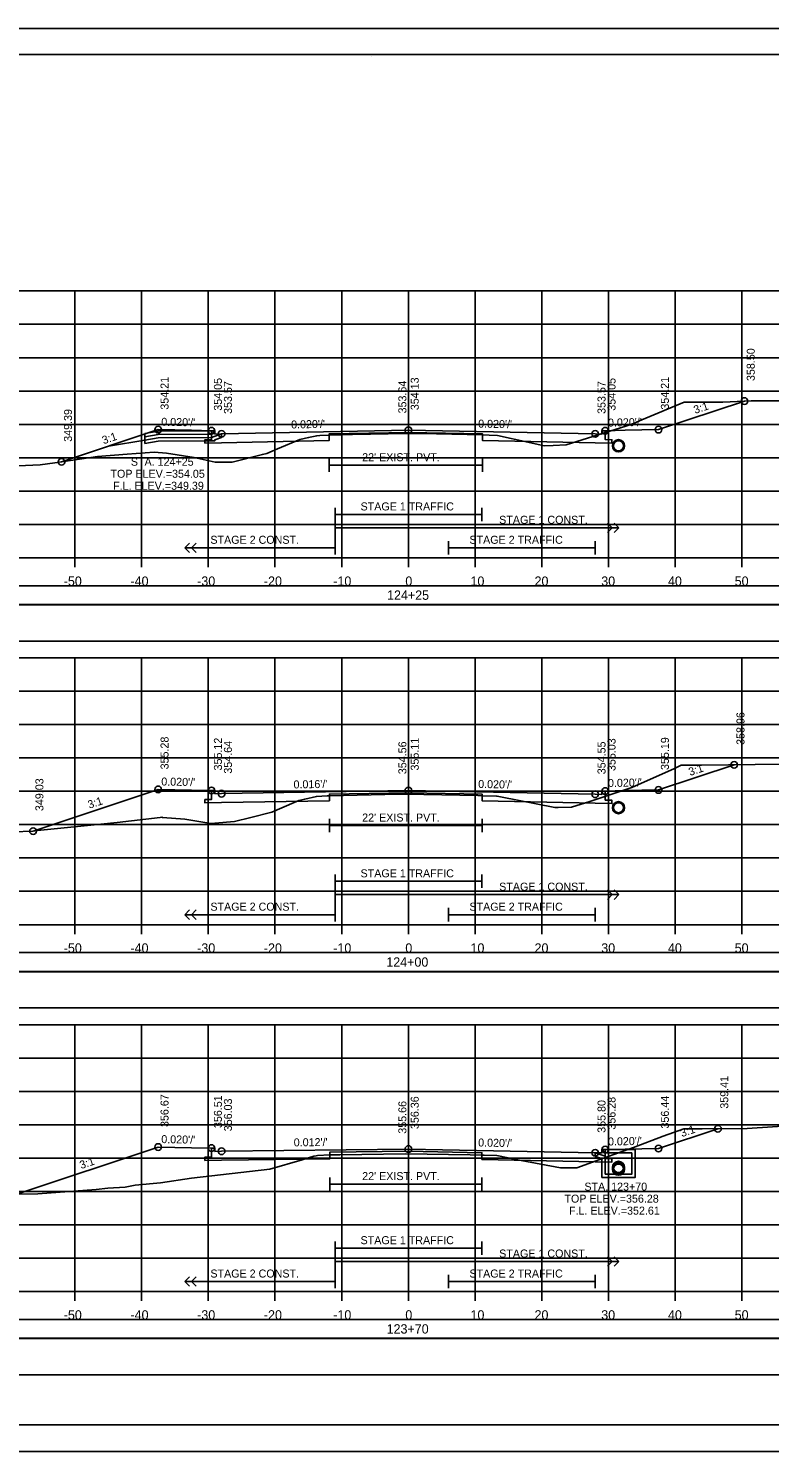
# Model space of a CAD drawing. Extents: x 1368122 to 1710785, y 373130 to 557566.
# Drawn here: x 1368631.9 to 1368743, y 376330.4 to 376543.7 of the extents above; entities that cross this region are included whole.
import ezdxf

# ---------------------------------------------------------------- set-up
doc = ezdxf.new("R2010")
doc.units = 0
for name, color, linetype in [('R_Alt Surface', 7, 'Continuous'), ('R_Axis', 7, 'Continuous'), ('R_Axis Annot', 7, 'Continuous'), ('R_Border', 7, 'Continuous'), ('R_Exist Surface', 7, 'Continuous'), ('R_Fin Surface', 7, 'Continuous'), ('R_Grid', 7, 'Continuous'), ('R_No Plot', 7, 'Continuous'), ('R_Striping', 7, 'Continuous'), ('R_Water', 7, 'Continuous'), ('R_Water Annot', 7, 'Continuous'), ('R_Xsect Elev', 7, 'Continuous'), ('R_Xsect Slope', 7, 'Continuous')]:
    doc.layers.add(name, color=color, linetype=linetype)

msp = doc.modelspace()

# ---------------------------------------------------------------- linework, layer by layer
for points in [[(1368539.73, 376451.9), (1368838.03, 376451.9), (1368838.03, 376457.32), (1368539.73, 376457.32)], [(1368539.73, 376396.9), (1368838.03, 376396.9), (1368838.03, 376402.32), (1368539.73, 376402.32)], [(1368539.73, 376341.9), (1368838.03, 376341.9), (1368838.03, 376347.32), (1368539.73, 376347.32)]]:
    msp.add_lwpolyline(points, close=True)
at = {"layer": 'R_Alt Surface'}
for points in [[(1368718.38, 376483.43), (1368718.38, 376482.09), (1368719.38, 376482.07), (1368719.38, 376481.57), (1368716.88, 376481.62), (1368700.01, 376481.96), (1368700.01, 376482.96), (1368688.88, 376483.18), (1368676.99, 376482.94), (1368676.99, 376481.94), (1368660.88, 376481.62), (1368658.38, 376481.57), (1368658.38, 376482.07), (1368659.38, 376482.09), (1368659.38, 376483.43)], [(1368676.99, 376479.26), (1368676.99, 376477.26)], [(1368700.01, 376479.26), (1368700.01, 376477.26)], [(1368676.99, 376478.26), (1368700.01, 376478.26)], [(1368718.38, 376429.41), (1368718.38, 376428.06), (1368719.38, 376428.04), (1368719.38, 376427.54), (1368716.88, 376427.59), (1368699.96, 376427.93), (1368699.96, 376428.93), (1368688.88, 376429.16), (1368677.04, 376428.96), (1368677.04, 376427.96), (1368660.88, 376427.69), (1368658.38, 376427.64), (1368658.38, 376428.14), (1368659.38, 376428.16), (1368659.38, 376429.5)], [(1368677.04, 376425.24), (1368677.04, 376423.24)], [(1368677.04, 376424.24), (1368699.96, 376424.24)], [(1368699.96, 376425.24), (1368699.96, 376423.24)], [(1368718.38, 376375.66), (1368718.38, 376374.32), (1368719.38, 376374.3), (1368719.38, 376373.8), (1368716.88, 376373.85), (1368699.9, 376374.19), (1368699.9, 376375.19), (1368688.88, 376375.41), (1368677.09, 376375.27), (1368677.09, 376374.27), (1368660.88, 376374.08), (1368658.38, 376374.03), (1368658.38, 376374.53), (1368659.38, 376374.55), (1368659.38, 376375.89)], [(1368677.09, 376371.49), (1368677.09, 376369.49)], [(1368677.09, 376370.49), (1368699.9, 376370.49)], [(1368699.9, 376371.49), (1368699.9, 376369.49)]]:
    msp.add_lwpolyline(points, dxfattribs=at)
for points in [[(1368539.73, 376457.37), (1368838.03, 376457.37), (1368838.03, 376460.19), (1368539.73, 376460.19)], [(1368539.73, 376402.37), (1368838.03, 376402.37), (1368838.03, 376405.19), (1368539.73, 376405.19)], [(1368539.73, 376347.37), (1368838.03, 376347.37), (1368838.03, 376350.19), (1368539.73, 376350.19)]]:
    msp.add_lwpolyline(points, close=True, dxfattribs=at)
at = {"layer": 'R_Axis'}
for p, q in [((1368538.88, 376464.38), (1368838.88, 376464.38)), ((1368638.88, 376462.98), (1368638.88, 376464.38)), ((1368648.88, 376462.98), (1368648.88, 376464.38)), ((1368658.88, 376462.98), (1368658.88, 376464.38)), ((1368668.88, 376462.98), (1368668.88, 376464.38)), ((1368678.88, 376462.98), (1368678.88, 376464.38)), ((1368688.88, 376462.98), (1368688.88, 376464.38)), ((1368698.88, 376462.98), (1368698.88, 376464.38)), ((1368708.88, 376462.98), (1368708.88, 376464.38)), ((1368718.88, 376462.98), (1368718.88, 376464.38)), ((1368728.88, 376462.98), (1368728.88, 376464.38)), ((1368738.88, 376462.98), (1368738.88, 376464.38)), ((1368538.88, 376409.38), (1368838.88, 376409.38)), ((1368638.88, 376407.98), (1368638.88, 376409.38)), ((1368648.88, 376407.98), (1368648.88, 376409.38)), ((1368658.88, 376407.98), (1368658.88, 376409.38)), ((1368668.88, 376407.98), (1368668.88, 376409.38)), ((1368678.88, 376407.98), (1368678.88, 376409.38)), ((1368688.88, 376407.98), (1368688.88, 376409.38)), ((1368698.88, 376407.98), (1368698.88, 376409.38)), ((1368708.88, 376407.98), (1368708.88, 376409.38)), ((1368718.88, 376407.98), (1368718.88, 376409.38)), ((1368728.88, 376407.98), (1368728.88, 376409.38)), ((1368738.88, 376407.98), (1368738.88, 376409.38)), ((1368538.88, 376354.38), (1368838.88, 376354.38)), ((1368638.88, 376352.98), (1368638.88, 376354.38)), ((1368648.88, 376352.98), (1368648.88, 376354.38)), ((1368658.88, 376352.98), (1368658.88, 376354.38)), ((1368668.88, 376352.98), (1368668.88, 376354.38)), ((1368678.88, 376352.98), (1368678.88, 376354.38)), ((1368688.88, 376352.98), (1368688.88, 376354.38)), ((1368698.88, 376352.98), (1368698.88, 376354.38)), ((1368708.88, 376352.98), (1368708.88, 376354.38)), ((1368718.88, 376352.98), (1368718.88, 376354.38)), ((1368728.88, 376352.98), (1368728.88, 376354.38)), ((1368738.88, 376352.98), (1368738.88, 376354.38))]:
    msp.add_line(p, q, dxfattribs=at)
at = {"layer": 'R_Border'}
for p, q in [((1368530.88, 376539.84), (1368847.06, 376539.84)), ((1368683.4, 376539.58), (1368683.4, 376539.58)), ((1368683.4, 376539.58), (1368683.4, 376539.58)), ((1368847.06, 376334.38), (1368530.88, 376334.38))]:
    msp.add_line(p, q, dxfattribs=at)
at = {"layer": 'R_Exist Surface'}
for points in [[(1368629.27, 376478.11), (1368633.68, 376478.32), (1368635.87, 376478.61), (1368642.3, 376479.56), (1368646.73, 376479.92), (1368650.76, 376480.23), (1368652.61, 376480.06), (1368656.78, 376479.4), (1368659.93, 376478.72), (1368661.22, 376478.72), (1368662.48, 376478.73), (1368666.99, 376479.88), (1368667.67, 376480.04), (1368669.24, 376480.7), (1368672.61, 376482.1), (1368673.93, 376482.4), (1368675.14, 376482.68), (1368675.59, 376482.7), (1368676.99, 376482.77), (1368680.48, 376482.85), (1368688.56, 376483.03), (1368693.11, 376482.94), (1368700.01, 376482.8), (1368700.98, 376482.75), (1368702.23, 376482.69), (1368706.76, 376481.73), (1368709.25, 376481.15), (1368710.58, 376481.22), (1368712.54, 376481.3), (1368721.46, 376484.13), (1368722.61, 376484.5), (1368723.89, 376485.04), (1368730.22, 376487.71), (1368735.28, 376487.71), (1368736.03, 376487.7), (1368739.27, 376487.88), (1368740.24, 376487.93), (1368745.9, 376487.9)], [(1368629.62, 376423.31), (1368632.58, 376423.4), (1368633.28, 376423.5), (1368642.3, 376424.38), (1368645.22, 376424.7), (1368651.68, 376425.45), (1368651.92, 376425.48), (1368652.02, 376425.47), (1368655.37, 376425.19), (1368659.26, 376424.57), (1368659.85, 376424.58), (1368662.81, 376424.83), (1368665.26, 376425.44), (1368668.43, 376426.24), (1368671.77, 376427.71), (1368672.46, 376428.01), (1368673.35, 376428.22), (1368675.1, 376428.62), (1368676.71, 376428.7), (1368677.04, 376428.72), (1368687.47, 376428.93), (1368688.5, 376428.95), (1368699.27, 376428.74), (1368699.96, 376428.72), (1368702.09, 376428.63), (1368702.19, 376428.63), (1368702.71, 376428.53), (1368710.82, 376426.96), (1368711.32, 376426.95), (1368713.35, 376427), (1368716.06, 376427.86), (1368722.38, 376429.93), (1368728.77, 376432.81), (1368729.79, 376433.27), (1368732.8, 376433.28), (1368744.91, 376433.44)], [(1368629.93, 376368.98), (1368633.33, 376369.05), (1368642.07, 376369.68), (1368643.82, 376369.86), (1368646.42, 376370.02), (1368647.92, 376370.32), (1368651.72, 376370.69), (1368656.36, 376371.39), (1368668.1, 376372.72), (1368672.96, 376374.13), (1368674.69, 376374.66), (1368675.06, 376374.75), (1368675.28, 376374.76), (1368677.09, 376374.86), (1368678.59, 376374.88), (1368688.43, 376375.05), (1368698.15, 376374.87), (1368699.9, 376374.83), (1368700.25, 376374.82), (1368702.14, 376374.76), (1368705.8, 376374.05), (1368711.69, 376372.91), (1368713.3, 376372.91), (1368714.13, 376372.91), (1368718.13, 376374.36), (1368722.6, 376375.97), (1368727.06, 376377.67), (1368730.16, 376378.76), (1368732.91, 376378.76), (1368739.64, 376378.84), (1368747.99, 376379.36)]]:
    msp.add_lwpolyline(points, dxfattribs=at)
for centre in [(1368720.38, 376481.18), (1368720.38, 376426.92)]:
    msp.add_circle(centre, 0.917, dxfattribs=at)
at = {"layer": 'R_Fin Surface'}
for points in [[(1368636.9, 376478.77), (1368651.38, 376483.59), (1368656.38, 376483.49), (1368659.38, 376483.43), (1368659.88, 376483.43), (1368659.88, 376482.93), (1368660.88, 376482.95), (1368688.88, 376483.51), (1368716.88, 376482.95), (1368717.88, 376482.93), (1368717.88, 376483.43), (1368718.38, 376483.43), (1368721.38, 376483.49), (1368726.38, 376483.59), (1368739.25, 376487.88)], [(1368632.62, 376423.41), (1368651.38, 376429.66), (1368656.38, 376429.56), (1368659.38, 376429.5), (1368659.88, 376429.5), (1368659.88, 376429), (1368660.88, 376429.02), (1368688.88, 376429.49), (1368716.88, 376428.93), (1368717.88, 376428.91), (1368717.88, 376429.41), (1368718.38, 376429.41), (1368721.38, 376429.47), (1368726.38, 376429.57), (1368737.71, 376433.34)], [(1368630.18, 376368.98), (1368651.38, 376376.05), (1368656.38, 376375.95), (1368659.38, 376375.89), (1368659.88, 376375.89), (1368659.88, 376375.39), (1368660.88, 376375.41), (1368688.88, 376375.74), (1368716.88, 376375.18), (1368717.88, 376375.16), (1368717.88, 376375.66), (1368718.38, 376375.66), (1368721.38, 376375.72), (1368726.38, 376375.82), (1368735.28, 376378.79)]]:
    msp.add_lwpolyline(points, dxfattribs=at)
at = {"layer": 'R_Grid'}
for p, q in [((1368538.88, 376504.38), (1368838.88, 376504.38)), ((1368638.88, 376464.38), (1368638.88, 376504.38)), ((1368648.88, 376464.38), (1368648.88, 376504.38)), ((1368658.88, 376464.38), (1368658.88, 376504.38)), ((1368668.88, 376464.38), (1368668.88, 376504.38)), ((1368678.88, 376464.38), (1368678.88, 376504.38)), ((1368688.88, 376464.38), (1368688.88, 376504.38)), ((1368698.88, 376464.38), (1368698.88, 376504.38)), ((1368708.88, 376464.38), (1368708.88, 376504.38)), ((1368718.88, 376464.38), (1368718.88, 376504.38)), ((1368728.88, 376464.38), (1368728.88, 376504.38)), ((1368738.88, 376464.38), (1368738.88, 376504.38)), ((1368538.88, 376499.38), (1368838.88, 376499.38)), ((1368538.88, 376494.38), (1368838.88, 376494.38)), ((1368538.88, 376489.38), (1368838.88, 376489.38)), ((1368538.88, 376484.38), (1368838.88, 376484.38)), ((1368538.88, 376479.38), (1368838.88, 376479.38)), ((1368538.88, 376474.38), (1368838.88, 376474.38)), ((1368538.88, 376469.38), (1368838.88, 376469.38)), ((1368538.88, 376464.38), (1368838.88, 376464.38)), ((1368538.88, 376449.38), (1368838.88, 376449.38)), ((1368638.88, 376409.38), (1368638.88, 376449.38)), ((1368648.88, 376409.38), (1368648.88, 376449.38)), ((1368658.88, 376409.38), (1368658.88, 376449.38)), ((1368668.88, 376409.38), (1368668.88, 376449.38)), ((1368678.88, 376409.38), (1368678.88, 376449.38)), ((1368688.88, 376409.38), (1368688.88, 376449.38)), ((1368698.88, 376409.38), (1368698.88, 376449.38)), ((1368708.88, 376409.38), (1368708.88, 376449.38)), ((1368718.88, 376409.38), (1368718.88, 376449.38)), ((1368728.88, 376409.38), (1368728.88, 376449.38)), ((1368738.88, 376409.38), (1368738.88, 376449.38)), ((1368538.88, 376444.38), (1368838.88, 376444.38)), ((1368538.88, 376439.38), (1368838.88, 376439.38)), ((1368538.88, 376434.38), (1368838.88, 376434.38)), ((1368538.88, 376429.38), (1368838.88, 376429.38)), ((1368538.88, 376424.38), (1368838.88, 376424.38)), ((1368538.88, 376419.38), (1368838.88, 376419.38)), ((1368538.88, 376414.38), (1368838.88, 376414.38)), ((1368538.88, 376409.38), (1368838.88, 376409.38)), ((1368538.88, 376394.38), (1368838.88, 376394.38)), ((1368638.88, 376354.38), (1368638.88, 376394.38)), ((1368648.88, 376354.38), (1368648.88, 376394.38)), ((1368658.88, 376354.38), (1368658.88, 376394.38)), ((1368668.88, 376354.38), (1368668.88, 376394.38)), ((1368678.88, 376354.38), (1368678.88, 376394.38)), ((1368688.88, 376354.38), (1368688.88, 376394.38)), ((1368698.88, 376354.38), (1368698.88, 376394.38)), ((1368708.88, 376354.38), (1368708.88, 376394.38)), ((1368718.88, 376354.38), (1368718.88, 376394.38)), ((1368728.88, 376354.38), (1368728.88, 376394.38)), ((1368738.88, 376354.38), (1368738.88, 376394.38)), ((1368538.88, 376389.38), (1368838.88, 376389.38)), ((1368538.88, 376384.38), (1368838.88, 376384.38)), ((1368538.88, 376379.38), (1368838.88, 376379.38)), ((1368538.88, 376374.38), (1368838.88, 376374.38)), ((1368538.88, 376369.38), (1368838.88, 376369.38)), ((1368538.88, 376364.38), (1368838.88, 376364.38)), ((1368538.88, 376359.38), (1368838.88, 376359.38)), ((1368538.88, 376354.38), (1368838.88, 376354.38))]:
    msp.add_line(p, q, dxfattribs=at)
at = {"layer": 'R_No Plot'}
for p, q in [((1368518.48, 376543.73), (1368851.81, 376543.73)), ((1368518.48, 376330.4), (1368851.81, 376330.4))]:
    msp.add_line(p, q, dxfattribs=at)
for points in [[(1368518.47, 376543.73), (1368851.81, 376543.73), (1368851.81, 376330.4), (1368518.47, 376330.4)], [(1368764.8, 376539.84), (1368784.42, 376539.84), (1368784.42, 376529.96), (1368800.53, 376529.96), (1368823.73, 376529.96), (1368823.85, 376501.8), (1368847.06, 376501.8), (1368847.06, 376334.38), (1368530.88, 376334.38), (1368530.88, 376539.84)]]:
    msp.add_lwpolyline(points, close=True, dxfattribs=at)
for centre, radius in [((1368739.25, 376487.88), 0.5), ((1368651.38, 376483.59), 0.5), ((1368659.38, 376483.43), 0.5), ((1368660.88, 376482.95), 0.5), ((1368688.88, 376483.51), 0.5), ((1368716.88, 376482.95), 0.5), ((1368718.38, 376483.43), 0.5), ((1368726.38, 376483.59), 0.5), ((1368636.9, 376478.77), 0.5), ((1368737.71, 376433.34), 0.5), ((1368651.38, 376429.66), 0.5), ((1368659.38, 376429.5), 0.5), ((1368688.88, 376429.49), 0.5), ((1368726.38, 376429.57), 0.5), ((1368660.88, 376429.02), 0.5), ((1368716.88, 376428.93), 0.5), ((1368718.38, 376429.41), 0.5), ((1368632.62, 376423.41), 0.5), ((1368735.28, 376378.79), 0.5), ((1368651.38, 376376.05), 0.5), ((1368659.38, 376375.89), 0.5), ((1368660.88, 376375.41), 0.5), ((1368688.88, 376375.74), 0.5), ((1368716.88, 376375.18), 0.5), ((1368718.38, 376375.66), 0.5), ((1368726.38, 376375.82), 0.5), ((1368720.38, 376372.99), 0.917), ((1368720.38, 376372.74), 0.917)]:
    msp.add_circle(centre, radius, dxfattribs=at)
at = {"layer": 'R_Striping'}
for p, q in [((1368719.42, 376468.88), (1368718.71, 376469.59)), ((1368718.71, 376468.17), (1368719.42, 376468.88)), ((1368720.42, 376468.88), (1368719.71, 376469.59)), ((1368719.71, 376468.17), (1368720.42, 376468.88)), ((1368655.38, 376465.88), (1368656.09, 376466.59)), ((1368656.38, 376465.88), (1368657.09, 376466.59)), ((1368655.38, 376465.88), (1368677.88, 376465.88)), ((1368656.09, 376465.17), (1368655.38, 376465.88)), ((1368657.09, 376465.17), (1368656.38, 376465.88)), ((1368719.42, 376413.88), (1368718.71, 376414.59)), ((1368718.71, 376413.17), (1368719.42, 376413.88)), ((1368720.42, 376413.88), (1368719.71, 376414.59)), ((1368719.71, 376413.17), (1368720.42, 376413.88)), ((1368655.38, 376410.88), (1368656.09, 376411.59)), ((1368655.38, 376410.88), (1368677.88, 376410.88)), ((1368656.09, 376410.17), (1368655.38, 376410.88)), ((1368656.38, 376410.88), (1368657.09, 376411.59)), ((1368657.09, 376410.17), (1368656.38, 376410.88)), ((1368719.42, 376358.88), (1368718.71, 376359.59)), ((1368720.42, 376358.88), (1368719.71, 376359.59)), ((1368718.71, 376358.17), (1368719.42, 376358.88)), ((1368719.71, 376358.17), (1368720.42, 376358.88)), ((1368655.38, 376355.88), (1368656.09, 376356.59)), ((1368655.38, 376355.88), (1368677.88, 376355.88)), ((1368656.09, 376355.17), (1368655.38, 376355.88)), ((1368656.38, 376355.88), (1368657.09, 376356.59)), ((1368657.09, 376355.17), (1368656.38, 376355.88))]:
    msp.add_line(p, q, dxfattribs=at)
for points in [[(1368677.88, 376471.88), (1368677.88, 376464.88)], [(1368677.88, 376470.88), (1368699.88, 376470.88)], [(1368699.88, 376471.88), (1368699.88, 376469.88)], [(1368677.88, 376468.88), (1368720.42, 376468.88)], [(1368694.88, 376466.88), (1368694.88, 376464.88)], [(1368716.88, 376466.88), (1368716.88, 376464.88)], [(1368694.88, 376465.88), (1368716.88, 376465.88)], [(1368677.88, 376416.88), (1368677.88, 376409.88)], [(1368677.88, 376415.88), (1368699.88, 376415.88)], [(1368699.88, 376416.88), (1368699.88, 376414.88)], [(1368677.88, 376413.88), (1368720.42, 376413.88)], [(1368694.88, 376411.88), (1368694.88, 376409.88)], [(1368694.88, 376410.88), (1368716.88, 376410.88)], [(1368716.88, 376411.88), (1368716.88, 376409.88)], [(1368677.88, 376361.88), (1368677.88, 376354.88)], [(1368699.88, 376361.88), (1368699.88, 376359.88)], [(1368677.88, 376360.88), (1368699.88, 376360.88)], [(1368677.88, 376358.88), (1368720.42, 376358.88)], [(1368694.88, 376356.88), (1368694.88, 376354.88)], [(1368694.88, 376355.88), (1368716.88, 376355.88)], [(1368716.88, 376356.88), (1368716.88, 376354.88)]]:
    msp.add_lwpolyline(points, dxfattribs=at)
at = {"layer": 'R_Water'}
for p, q in [((1368651.38, 376483.35), (1368649.39, 376483.02)), ((1368659.38, 376483.43), (1368651.38, 376483.35)), ((1368649.38, 376482.02), (1368643.95, 376481.11)), ((1368649.38, 376481.52), (1368649.38, 376483.02)), ((1368651.38, 376482.85), (1368649.38, 376482.52)), ((1368651.38, 376482.35), (1368649.38, 376482.02)), ((1368651.38, 376481.85), (1368649.38, 376481.52)), ((1368659.38, 376482.93), (1368651.38, 376482.85)), ((1368659.38, 376482.43), (1368651.38, 376482.35)), ((1368659.38, 376481.93), (1368651.38, 376481.85)), ((1368716.88, 376375.18), (1368718.38, 376374.66)), ((1368716.88, 376374.65), (1368717.88, 376374.31)), ((1368718.05, 376375.5), (1368718.13, 376375.66)), ((1368718.05, 376375.5), (1368718.38, 376375.16)), ((1368722.88, 376375.66), (1368718.13, 376375.66)), ((1368722.38, 376375.16), (1368718.38, 376375.16)), ((1368718.38, 376374.16), (1368718.38, 376374.66)), ((1368722.38, 376374.16), (1368722.38, 376375.16)), ((1368722.88, 376374.16), (1368722.88, 376375.66)), ((1368717.88, 376374.16), (1368717.88, 376374.31))]:
    msp.add_line(p, q, dxfattribs=at)
for points in [[(1368659.38, 376483.43), (1368659.63, 376483.43), (1368659.71, 376483.27), (1368659.38, 376482.93)], [(1368659.38, 376482.43), (1368660.88, 376482.95), (1368660.88, 376482.42), (1368659.88, 376482.08), (1368659.88, 376481.93), (1368659.38, 376481.93)], [(1368716.88, 376374.65), (1368716.88, 376375.18)], [(1368722.88, 376374.16), (1368722.88, 376371.49), (1368720.38, 376371.49), (1368717.88, 376371.49), (1368717.88, 376374.16)], [(1368722.38, 376374.16), (1368722.38, 376371.99), (1368720.38, 376371.99), (1368718.38, 376371.99), (1368718.38, 376374.16)]]:
    msp.add_lwpolyline(points, dxfattribs=at)
for centre in [(1368720.38, 376481.18), (1368720.38, 376426.92), (1368720.38, 376372.99), (1368720.38, 376372.74)]:
    msp.add_circle(centre, 0.75, dxfattribs=at)
at = {"layer": 'R_Xsect Elev'}
for p, q in [((1368688.88, 376483.02), (1368688.88, 376493.02)), ((1368688.88, 376428.94), (1368688.88, 376438.94)), ((1368688.88, 376375.04), (1368688.88, 376385.04))]:
    msp.add_line(p, q, dxfattribs=at)

# ---------------------------------------------------------------- texts
at = {"layer": 'R_Axis Annot'}
for s, p in [('-50', (1368637.22, 376460.18)), ('-40', (1368647.22, 376460.18)), ('-30', (1368657.22, 376460.18)), ('-20', (1368667.22, 376460.18)), ('-10', (1368677.62, 376460.18)), ('0', (1368688.42, 376460.18)), ('10', (1368698.19, 376460.18)), ('20', (1368707.79, 376460.18)), ('30', (1368717.79, 376460.18)), ('40', (1368727.79, 376460.18)), ('50', (1368737.79, 376460.18)), ('124+25', (1368685.68, 376458.08)), ('-50', (1368637.22, 376405.18)), ('-40', (1368647.22, 376405.18)), ('-30', (1368657.22, 376405.18)), ('-20', (1368667.22, 376405.18)), ('-10', (1368677.62, 376405.18)), ('0', (1368688.42, 376405.18)), ('10', (1368698.19, 376405.18)), ('20', (1368707.79, 376405.18)), ('30', (1368717.79, 376405.18)), ('40', (1368727.79, 376405.18)), ('50', (1368737.79, 376405.18)), ('124+00', (1368685.57, 376403.08)), ('-50', (1368637.22, 376350.18)), ('-40', (1368647.22, 376350.18)), ('-30', (1368657.22, 376350.18)), ('-20', (1368667.22, 376350.18)), ('-10', (1368677.62, 376350.18)), ('0', (1368688.42, 376350.18)), ('10', (1368698.19, 376350.18)), ('20', (1368707.79, 376350.18)), ('30', (1368717.79, 376350.18)), ('40', (1368727.79, 376350.18)), ('50', (1368737.79, 376350.18)), ('123+70', (1368685.62, 376348.08))]:
    msp.add_text(s, height=1.4, dxfattribs=at).set_placement(p)
at = {"layer": 'R_Striping'}
for s, p in [('STAGE 1 TRAFFIC', (1368681.71, 376471.48)), ('STAGE 1 CONST.', (1368702.49, 376469.48)), ('STAGE 2 CONST.', (1368659.2, 376466.48)), ('STAGE 2 TRAFFIC', (1368698.03, 376466.48)), ('STAGE 1 TRAFFIC', (1368681.71, 376416.48)), ('STAGE 1 CONST.', (1368702.49, 376414.48)), ('STAGE 2 CONST.', (1368659.2, 376411.48)), ('STAGE 2 TRAFFIC', (1368698.03, 376411.48)), ('STAGE 1 TRAFFIC', (1368681.71, 376361.48)), ('STAGE 1 CONST.', (1368702.49, 376359.48)), ('STAGE 2 CONST.', (1368659.2, 376356.48)), ('STAGE 2 TRAFFIC', (1368698.03, 376356.48))]:
    msp.add_text(s, height=1.2, dxfattribs=at).set_placement(p)
at = {"layer": 'R_Water'}
for p in [(1368681.95, 376478.86), (1368681.95, 376424.84), (1368681.95, 376371.09)]:
    msp.add_text("22' EXIST. PVT.", height=1.2, dxfattribs=at).set_placement(p)
at = {"layer": 'R_Water Annot'}
for s, p in [('STA. 124+25', (1368647.28, 376478.18)), ('TOP ELEV.=354.05', (1368644.22, 376476.38)), ('F.L. ELEV.=349.39', (1368644.61, 376474.58)), ('STA. 123+70', (1368715.26, 376369.51)), ('TOP ELEV.=356.28', (1368712.27, 376367.71)), ('F.L. ELEV.=352.61', (1368712.96, 376365.91))]:
    msp.add_text(s, height=1.2, dxfattribs=at).set_placement(p)
at = {"layer": 'R_Xsect Elev'}
for s, p in [('358.50', (1368740.8, 376490.88)), ('354.21', (1368652.93, 376486.59)), ('354.05', (1368660.93, 376486.43)), ('353.57', (1368662.43, 376485.95)), ('353.64', (1368688.58, 376486.02)), ('354.13', (1368690.43, 376486.51)), ('353.57', (1368718.43, 376485.95)), ('354.05', (1368719.93, 376486.43)), ('354.21', (1368727.93, 376486.59)), ('349.39', (1368638.45, 376481.77)), ('358.96', (1368739.26, 376436.34)), ('355.28', (1368652.93, 376432.66)), ('355.12', (1368660.93, 376432.5)), ('354.64', (1368662.43, 376432.02)), ('354.56', (1368688.58, 376431.94)), ('355.11', (1368690.43, 376432.49)), ('354.55', (1368718.43, 376431.93)), ('355.03', (1368719.93, 376432.41)), ('355.19', (1368727.93, 376432.57)), ('349.03', (1368634.17, 376426.41)), ('359.41', (1368736.83, 376381.79)), ('356.67', (1368652.93, 376379.05)), ('356.51', (1368660.93, 376378.89)), ('356.03', (1368662.43, 376378.41)), ('356.36', (1368690.43, 376378.74)), ('355.80', (1368718.43, 376378.18)), ('356.28', (1368719.93, 376378.66)), ('356.44', (1368727.93, 376378.82)), ('355.66', (1368688.58, 376378.04))]:
    msp.add_text(s, height=1.2, rotation=90, dxfattribs=at).set_placement(p)
at = {"layer": 'R_Xsect Slope'}
for s, rotation, p in [('3:1', 18.4349, (1368731.87, 376485.95)), ("0.020'/'", 1.1458, (1368718.81, 376484.04)), ("0.020'/'", 358.8542, (1368651.83, 376484.18)), ("0.020'/'", 1.1458, (1368671.31, 376483.76)), ("0.020'/'", 358.8542, (1368699.33, 376483.9)), ('3:1', 18.4349, (1368643.19, 376481.39)), ('3:1', 18.4349, (1368731.1, 376431.67)), ("0.020'/'", 358.8542, (1368651.83, 376430.25)), ("0.016'/'", 0.9449, (1368671.67, 376429.8)), ("0.020'/'", 358.8542, (1368699.33, 376429.88)), ("0.020'/'", 1.1458, (1368718.81, 376430.01)), ('3:1', 18.4349, (1368641.05, 376426.75)), ('3:1', 18.4349, (1368729.88, 376377.52)), ("0.020'/'", 358.8542, (1368651.83, 376376.64)), ("0.012'/'", 0.6852, (1368671.7, 376376.14)), ("0.020'/'", 358.8542, (1368699.33, 376376.13)), ("0.020'/'", 1.1458, (1368718.81, 376376.27)), ('3:1', 18.4349, (1368639.83, 376372.73))]:
    msp.add_text(s, height=1.2, rotation=rotation, dxfattribs=at).set_placement(p)

doc.saveas('drawing.dxf')
